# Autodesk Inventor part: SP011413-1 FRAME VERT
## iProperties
Created: 2013-01
Part Number: SP011413-1 FRAME VERT
Material: Aluminum-6061
Description: PROFILE 45X45 F
Document SubType Name: Modeling
Designer: Administrator
Stock Number: 20.1033 PROFILE 45X45 F
Density: 2.71 g/cm^3
Mass: 2653.36 g
Surface Area: 7129.2 cm^2
Volume: 979.101 cm^3
FINISH: CLEAR ANODIZED
Author: Administrator
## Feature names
1. Extrusion1
